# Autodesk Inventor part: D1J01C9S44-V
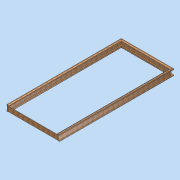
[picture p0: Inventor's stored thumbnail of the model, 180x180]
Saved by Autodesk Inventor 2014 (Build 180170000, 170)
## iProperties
Created: 2012-07
Part Number: D1J01C9S44-V
Document SubType Name: Modeling
Designer: david.appleford
Mass: 10000 g
Surface Area: 18673.1 cm^2
Volume: 18665.2 cm^3
Density: 0.535757 g/cm^3
Cost Center: £153.00
Description: Door J01 Frame Assembly - Single Wall - 9 Locks
Material: 000 Redwood
Appearance: Wood (Oak)
Justset: False
Author: david.appleford
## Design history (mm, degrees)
sketch "Sketch1"
  geometry: L1 (0, 2034)-(936, 2034); L2 (936, 2034)-(936, 0); L3 (0, 0)-(0, 2034); L4 (60, 1974)-(876, 1974); L5 (876, 1974)-(876, 0); L6 (60, 0)-(60, 1974); L7 (936, 0)-(876, 0); L8 (60, 0)-(0, 0); 1 further point
  constraints: 16 end point, 1 coincident, 1 collinear
  dimensions: "d2" = 936 distance between parallel lines of L2 L3 (= d3 + 2 x d4); "d3" = 816 distance between parallel lines of L5 L6; "d4" = 60 distance between parallel lines of L6 L3; "d6" = 60 distance between parallel lines of L4 L1 (derived); "d7" = 2034 distance between parallel lines of L8 L1; "d8" = 1974 distance between parallel lines of L7 L4
extrude "Extrusion1" new body sketch "Sketch1" distance "d9" = 106; taper "d10" = 0 deg
sketch "Sketch2"
  geometry: L1 (0, -13)-(13, -13); L2 (13, -13)-(13, -93); L3 (13, -93)-(0, -93); L4 (0, -93)-(0, -13); L5 (936, -13)-(923, -13); L6 (923, -13)-(923, -93); L7 (923, -93)-(936, -93); L8 (936, -93)-(936, -13); L9 (936, 0)-(936, -106) reference; L10 (0, 0)-(0, -106) reference; L11 (60, 0)-(0, 0) reference; L12 (0, -106)-(936, -106) reference
  constraints: 16 end point, 4 collinear
  dimensions: "d11" = 13 distance between parallel lines of L2 L4; "d12" = 13 distance between parallel lines of L8 L6 (= d11); "d13" = 13 distance between parallel lines of L11 L1; "d14" = 13 distance between parallel lines of L12 L3; "d15" = 80 distance between parallel lines of L3 L1 (derived)
extrude "Extrusion2" cut sketch "Sketch2" stored distance "d16" = 106; taper "d17" = 0 deg
sketch "Sketch3"
  geometry: L1 (0, -2034)-(0, 0) reference; L2 (80, 0)-(80, -2034) reference; L3 (0, 0)-(80, 0); L4 (80, 0)-(80, -13); L5 (80, -13)-(0, -13); L6 (0, -13)-(0, 0); 1 further point
  constraints: 8 end point, 1 point on line
  dimensions: "d18" = 13 distance between parallel lines of L5 L3
extrude "Extrusion3" cut sketch "Sketch3" stored distance "d19" = 106; taper "d20" = 0 deg
sketch "Sketch4"
  geometry: L1 (45, 1989)-(891, 1989); L2 (891, 1989)-(891, 0); L3 (45, 0)-(45, 1989); L4 (0, 0)-(0, 2034) reference; L5 (0, 2034)-(936, 2034) reference; L6 (936, 2034)-(936, 0) reference; L7 (936, 0)-(876, 0) reference; L8 (60, 1974)-(60, 0) reference; L9 (876, 1974)-(60, 1974) reference; L10 (876, 0)-(876, 1974) reference; L11 (891, 0)-(876, 0); L12 (60, 0)-(45, 0)
  constraints: 12 end point, 2 collinear
  dimensions: "d21" = 45 distance between parallel lines of L3 L4; "d22" = 45 distance between parallel lines of L5 L1 (= d21); "d23" = 45 distance between parallel lines of L6 L2 (= d21)
extrude "Extrusion4" cut sketch "Sketch4" distance "d24" = 55; taper "d25" = 0 deg
sketch "Sketch5"
  geometry: L1 (-901, 1999)-(-35, 1999); L2 (-35, 1999)-(-35, 0); L3 (-901, 0)-(-901, 1999); L4 (0, 2034)-(-936, 2034) reference; L5 (-936, 2034)-(-936, 0) reference; L6 (0, 0)-(0, 2034) reference; L7 (-60, 0)-(0, 0) reference; L8 (-876, 0)-(-876, 1974) reference; L9 (-60, 1974)-(-60, 0) reference; L10 (-876, 1974)-(-60, 1974) reference; L11 (-35, 0)-(-60, 0); L12 (-876, 0)-(-901, 0)
  constraints: 12 end point, 2 collinear
  dimensions: "d26" = 35 distance between parallel lines of L1 L4; "d27" = 35 distance between parallel lines of L3 L5 (= d26); "d28" = 35 distance between parallel lines of L6 L2 (= d26)
extrude "Extrusion5" cut sketch "Sketch5" distance "d29" = 24; taper "d30" = 0 deg
sketch "Sketch6"
  geometry: L1 (13, 0)-(13, -80) reference; L2 (923, -80)-(923, 0) reference; L3 (13, 0)-(923, 0); L4 (923, 0)-(923, -80); L5 (923, -80)-(13, -80); L6 (13, -80)-(13, 0); 1 further point
  constraints: 8 end point
extrude "Extrusion6" join sketch "Sketch6" distance "d31" = 9; taper "d32" = 0 deg
sketch "Sketch7"
  geometry: L1 (35, 1999)-(901, 1999); L2 (901, 1999)-(901, 0); L3 (35, 0)-(35, 1999); L4 (0, 2034)-(936, 2034) reference; L5 (0, 0)-(0, 2034) reference; L6 (936, 2034)-(936, 0) reference; L7 (45, 0)-(0, 0) reference; L8 (45, 0)-(45, 1989) reference; L9 (45, 1989)-(891, 1989) reference; L10 (891, 1989)-(891, 0) reference; L11 (901, 0)-(891, 0); L12 (45, 0)-(35, 0)
  constraints: 12 end point, 2 collinear
  dimensions: "d33" = 35 distance between parallel lines of L1 L4; "d34" = 35 distance between parallel lines of L5 L3 (= d33); "d35" = 35 distance between parallel lines of L6 L2 (= d33)
extrude "Extrusion7" cut sketch "Sketch7" distance "d36" = 8; taper "d37" = 0 deg
chamfer "Chamfer1" distance "d38" = 25; stored, may be unused: second distance "d39" = 5, angle "d40" = 45 deg
chamfer "Chamfer2" distance "d41" = 25; stored, may be unused: second distance "d42" = 5, angle "d43" = 45 deg
chamfer "Chamfer3" distance "d44" = 25; stored, may be unused: second distance "d45" = 5, angle "d46" = 45 deg
chamfer "Chamfer4" distance "d47" = 25; stored, may be unused: second distance "d48" = 5, angle "d49" = 45 deg
chamfer "Chamfer5" distance "d50" = 25; stored, may be unused: second distance "d51" = 5, angle "d52" = 45 deg
chamfer "Chamfer6" distance "d53" = 25; stored, may be unused: second distance "d54" = 5, angle "d55" = 45 deg
chamfer "Chamfer7" distance "d56" = 20; stored, may be unused: second distance "d57" = 5, angle "d58" = 45 deg
body "Solid1"
other parameters: "d1" = 2034, "d5" = 1974
